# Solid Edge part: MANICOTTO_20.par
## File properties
Subject: MANICOTTO_20
Author: Francesco
Template: Normal.par
Last saved by: f_grande
Revision: 10
Application: Solid Edge
Densità: 2712,000 kg/m^3
Precisione: 0,990
Tipo di contenuto documento: 0
Document Number: KR0132
Material: Alluminio, 1060
Stile della faccia: Alluminio
Stile di riempimento: ANSI38(Alluminio)
Stile virtuale: Alluminio lucidato
Coef. of Thermal Exp: 0.0
Thermal Conductivity: 221.0
Specific Heat: 920.0
Modulus of Elasticity: 68947570000.0
Poisson's Ratio: 0.33
Yield Stress: 27579028.0
Ultimate Stress: 68947570.0
Elongation: 0.0
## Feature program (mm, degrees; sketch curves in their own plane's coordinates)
sketch for "unnamed Protrusion 1" plane through (0, 0, 0) normal (0, -1, 0) x-axis (1, 0, 0)
  line (-13.0756, 21.9015) -> (10.9244, 21.9015)
  line (10.9244, 21.9015) -> (10.9244, 9.9015)
  line (10.9244, 9.9015) -> (9.9244, 9.9015)
  line (9.9244, 9.9015) -> (9.9244, -16.0985)
  line (9.9244, -16.0985) -> (-13.0756, -16.0985)
  line (-13.0756, -16.0985) -> (-13.0756, 21.9015)
  dimension (linear) = 13.0756
  dimension (linear) = 10.9244
extrude "unnamed Protrusion 1" add finite 96 along -normal
body pattern "unnamed BodyPattern 1"
pattern "unnamed Pattern 1"
chamfer "Smusso_1" setback 1
sketch for "ExtrudedCutout_1" plane through (-13.0756, 0, -6.5285) normal (0, -1, 0) x-axis (1, 0, 0)
  line (0, 28.43) -> (10, 28.43)
  line (10, 28.43) -> (10, 27.93)
  line (10, 27.93) -> (-10, 27.93)
  line (-10, 27.93) -> (-10, 28.43)
  line (-10, 28.43) -> (0, 28.43)
extrude "ExtrudedCutout_1" cut finite 121.764 along -normal
chamfer "Smusso_2" setback 0.5
sketch for "Foro_5" plane through (-13.0756, 0, -6.5285) normal (0, -1, 0) x-axis (1, 0, 0)
hole "Foro_5" diameter 20 through
sketch for "ExtrudedCutout_2" plane through (-13.0756, 0, 2.9015) normal (0, -1, 0) x-axis (1, 0, 0)
  circle centre (0, -1) radius 15.95
extrude "ExtrudedCutout_2" cut finite 4 along -normal
sketch for "ExtrudedCutout_3" plane through (-13.0756, 96, 2.9015) normal (0, 1, 0) x-axis (-1, 0, 0)
  circle centre (0, -1) radius 15.95
extrude "ExtrudedCutout_3" cut finite 4 along -normal
sketch for "ExtrudedCutout_4" plane through (-13.0756, 96, 2.9015) normal (0, 1, 0) x-axis (-1, 0, 0)
  line (0, -19) -> (8.25, -19)
  line (8.25, -19) -> (0, -2.9015)
  line (-8.25, -19) -> (0, -2.9015)
  line (0, -19) -> (-8.25, -19)
extrude "ExtrudedCutout_4" cut finite 206.4723 along -normal
chamfer "Smusso_4" setback 0.5
chamfer "Smusso_5" setback 0.5
sketch for "Foro_6" plane through (-30.3256, 48, 21.9015) normal (0, 0, 1) x-axis (0, 1, 0)
  hole centre (35, 0.25) bore radius 2.5
hole "Foro_6" diameter 5 through
sketch for "unnamed Hole 1" plane through (-30.3256, 48, 21.9015) normal (0, 0, 1) x-axis (0, 1, 0)
  hole centre (35, -37.25) bore radius 2.5
hole "unnamed Hole 1" through
sketch for "unnamed Hole 2" plane through (-30.3256, 48, 21.9015) normal (0, 0, 1) x-axis (0, 1, 0)
  hole centre (-35, -37.25) bore radius 2.5
hole "unnamed Hole 2" through
sketch for "unnamed Hole 3" plane through (-30.3256, 48, 21.9015) normal (0, 0, 1) x-axis (0, 1, 0)
  hole centre (-35, 0.25) bore radius 2.5
  dimension (linear) = 35
hole "unnamed Hole 3" through
pattern "unnamed Pattern 2" of "Foro_6", "unnamed Hole 1", "unnamed Hole 2", "unnamed Hole 3"
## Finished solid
Body 1: solid body, 28 faces, 74 edges, 44 vertices.
  Faces by surface: plane 19, cylinder 7, cone 2
  Edges by curve: line 54, circle 16, intersection 4
Bounding box of the edges (mm): 48.000 x 96.000 x 38.000, from (-37.0756, 0, -16.0985) to (10.9244, 96, 21.9015).
Cylindrical faces by radius (mm): R2.5 x4, R10 x1, R15.95 x2
Conical faces (half-angle, radius in mm at the cone's reference point): 45 deg R16.45 x2
Planar faces by outward normal: +x 2, +y 2, +z 3, -x 2, -y 2, -z 2, oblique 6
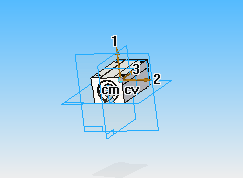
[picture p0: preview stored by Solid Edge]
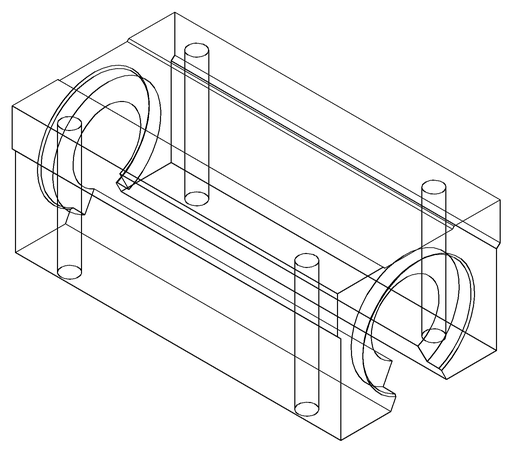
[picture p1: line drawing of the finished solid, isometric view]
